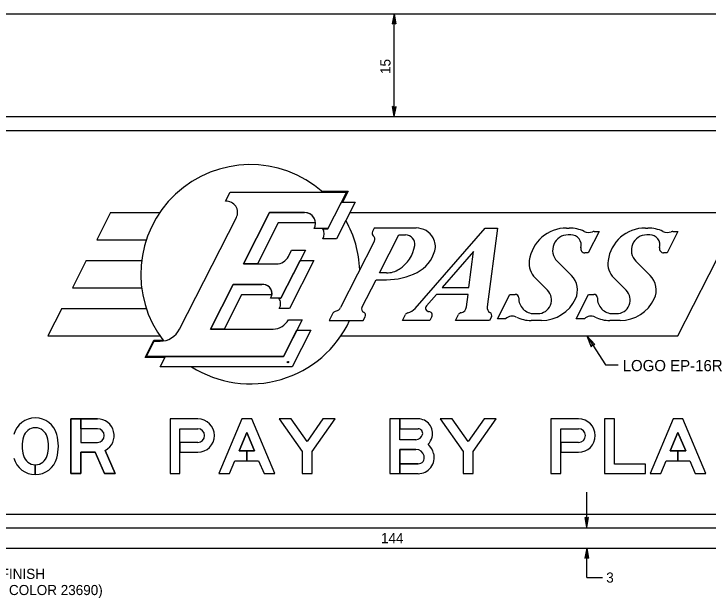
# Model space of a CAD drawing. Extents: x 60714 to 61340, y 9359 to 9729.
# Drawn here: x 60938.1 to 61130.7, y 9567 to 9729 of the extents above; entities that cross this region are included whole.
import ezdxf

# ---------------------------------------------------------------- set-up
doc = ezdxf.new("R2010")
doc.units = 0
for name, color, linetype in [('1', 7, 'Continuous'), ('2', 7, 'Continuous'), ('52', 7, 'Continuous'), ('GSBWFill', 7, 'Continuous'), ('SignPanel', 7, 'Continuous')]:
    doc.layers.add(name, color=color, linetype=linetype)

msp = doc.modelspace()

# ---------------------------------------------------------------- linework, layer by layer
at = {"layer": '1'}
for p, q in [((61043.58, 9700.47), (61043.58, 9728.97)), ((61097.05, 9639.67), (61102.28, 9631.67)), ((61102.28, 9631.67), (61105.72, 9631.67)), ((61097.05, 9586.47), (61097.05, 9596.36)), ((61097.05, 9572.66), (61097.05, 9580.77)), ((61097.05, 9572.66), (61101.45, 9572.66))]:
    msp.add_line(p, q, dxfattribs=at)
msp.add_circle((61014.12, 9632.42), 0.19, dxfattribs=at)
at = {"layer": '2'}
for p, q in [((60876.38, 9728.97), (61210.79, 9728.97)), ((60876.38, 9580.77), (61210.79, 9580.77))]:
    msp.add_line(p, q, dxfattribs=at)
at = {"layer": '52'}
for p, q in [((61043.58, 9728.97), (61043.05, 9726.21)), ((61043.58, 9728.97), (61043.31, 9726.32)), ((61043.58, 9728.97), (61044.03, 9726.19)), ((61043.58, 9728.97), (61043.77, 9726.31)), ((61043.05, 9726.21), (61043.54, 9726.41)), ((61043.54, 9726.41), (61044.03, 9726.19)), ((61043.58, 9700.47), (61043.14, 9703.25)), ((61043.63, 9703.03), (61043.14, 9703.25)), ((61043.58, 9700.47), (61043.4, 9703.13)), ((61043.58, 9700.47), (61044.12, 9703.23)), ((61043.58, 9700.47), (61043.86, 9703.12)), ((61044.12, 9703.23), (61043.63, 9703.03)), ((61097.05, 9639.67), (61098.29, 9636.63)), ((61099.31, 9637.3), (61097.05, 9639.67)), ((61098.29, 9636.63), (61098.68, 9637.18)), ((61098.68, 9637.18), (61099.31, 9637.3)), ((61097.03, 9586.55), (61096.59, 9589.32)), ((61097.08, 9589.1), (61096.59, 9589.32)), ((61097.03, 9586.55), (61096.85, 9589.21)), ((61097.03, 9586.55), (61097.57, 9589.31)), ((61097.03, 9586.55), (61097.31, 9589.2)), ((61097.57, 9589.31), (61097.08, 9589.1)), ((61097.05, 9580.77), (61096.51, 9578.01)), ((61097.05, 9580.77), (61096.77, 9578.12)), ((61097.05, 9580.77), (61097.49, 9577.99)), ((61097.05, 9580.77), (61097.23, 9578.11)), ((61096.51, 9578.01), (61097, 9578.21)), ((61097, 9578.21), (61097.49, 9577.99))]:
    msp.add_line(p, q, dxfattribs=at)
at = {"layer": 'GSBWFill'}
for p, q in [((60984.16, 9613.93), (60989.1, 9613.93)), ((60984.16, 9613.93), (60989.1, 9613.93)), ((60984.16, 9613.93), (60989.1, 9613.93)), ((61089.82, 9613.93), (61094.77, 9613.93)), ((61089.82, 9613.93), (61094.77, 9613.93)), ((61089.82, 9613.93), (61094.77, 9613.93)), ((60984.16, 9607.4), (60989.1, 9607.4)), ((61089.82, 9607.4), (61094.77, 9607.4)), ((60944.02, 9601.2), (60944.02, 9603.94)), ((60944.02, 9603.94), (60944.02, 9601.2)), ((60944.02, 9601.2), (60944.02, 9603.94)), ((60944.02, 9603.94), (60944.02, 9601.2)), ((61042.39, 9601.47), (61050.22, 9601.47))]:
    msp.add_line(p, q, dxfattribs=at)
for points in [[(60961.25, 9616.67), (60953.9, 9616.67), (60953.9, 9601.47), (60956.64, 9601.47), (60956.64, 9607.4), (60960.67, 9607.4), (60963.24, 9601.47), (60966.22, 9601.47), (60963.42, 9607.93)], [(60963.42, 9607.93), (60966.22, 9601.47), (60963.24, 9601.47), (60960.67, 9607.4), (60956.64, 9607.4), (60956.64, 9601.47), (60953.9, 9601.47), (60953.9, 9616.67), (60956.64, 9616.67), (60956.64, 9610.13), (60961.25, 9610.13)], [(60963.42, 9607.93), (60966.22, 9601.47), (60963.24, 9601.47), (60960.67, 9607.4), (60956.64, 9607.4), (60956.64, 9601.47), (60953.9, 9601.47), (60953.9, 9616.67), (60956.64, 9616.67), (60956.64, 9610.13), (60961.25, 9610.13)], [(60956.64, 9613.93), (60956.64, 9616.67), (60961.25, 9616.67)], [(60956.64, 9613.93), (60956.64, 9616.67), (60961.25, 9616.67)], [(60989.1, 9616.67), (60981.42, 9616.67), (60981.42, 9601.47), (60984.16, 9601.47), (60984.16, 9607.4)], [(60989.1, 9616.67), (60981.42, 9616.67), (60981.42, 9601.47), (60984.16, 9601.47), (60984.16, 9613.93)], [(60989.1, 9616.67), (60981.42, 9616.67), (60981.42, 9601.47), (60984.16, 9601.47), (60984.16, 9613.93)], [(61050.22, 9616.67), (61042.39, 9616.67), (61042.39, 9601.47)], [(61049.63, 9610.89), (61045.13, 9610.89), (61045.13, 9616.67), (61042.39, 9616.67), (61042.39, 9601.47), (61045.13, 9601.47)], [(61049.63, 9610.89), (61045.13, 9610.89), (61045.13, 9616.67), (61042.39, 9616.67), (61042.39, 9601.47), (61045.13, 9601.47)], [(61050.22, 9616.67), (61045.13, 9616.67), (61045.13, 9613.93), (61050.22, 9613.93)], [(61050.22, 9616.67), (61045.13, 9616.67), (61045.13, 9613.93), (61050.22, 9613.93)], [(61094.77, 9616.67), (61087.09, 9616.67), (61087.09, 9601.47), (61089.82, 9601.47), (61089.82, 9607.4)], [(61094.77, 9616.67), (61087.09, 9616.67), (61087.09, 9601.47), (61089.82, 9601.47), (61089.82, 9613.93)], [(61094.77, 9616.67), (61087.09, 9616.67), (61087.09, 9601.47), (61089.82, 9601.47), (61089.82, 9613.93)], [(60961.25, 9613.93), (60956.64, 9613.93), (60956.64, 9610.13), (60961.25, 9610.13)], [(60961.25, 9613.93), (60956.64, 9613.93)], [(60961.25, 9613.93), (60956.64, 9613.93)], [(60989.1, 9610.13), (60984.16, 9610.13), (60984.16, 9613.93)], [(61049.63, 9610.89), (61045.13, 9610.89), (61045.13, 9613.93), (61050.22, 9613.93)], [(61094.77, 9610.13), (61089.82, 9610.13), (61089.82, 9613.93)], [(60989.1, 9610.13), (60984.16, 9610.13), (60984.16, 9607.4), (60989.1, 9607.4)], [(60989.1, 9610.13), (60984.16, 9610.13), (60984.16, 9607.4), (60989.1, 9607.4)], [(61094.77, 9610.13), (61089.82, 9610.13), (61089.82, 9607.4), (61094.77, 9607.4)], [(61094.77, 9610.13), (61089.82, 9610.13), (61089.82, 9607.4), (61094.77, 9607.4)], [(61049.63, 9608.16), (61045.13, 9608.16), (61045.13, 9604.2), (61050.22, 9604.2)], [(61045.13, 9601.47), (61045.13, 9608.16), (61049.63, 9608.16)], [(61045.13, 9601.47), (61045.13, 9608.16), (61049.63, 9608.16)], [(61050.22, 9604.2), (61045.13, 9604.2), (61045.13, 9601.47), (61050.22, 9601.47)], [(61050.22, 9604.2), (61045.13, 9604.2), (61045.13, 9601.47), (61050.22, 9601.47)]]:
    msp.add_lwpolyline(points, dxfattribs=at)
for points in [[(60999.42, 9605.04), (61005.99, 9605.04), (61007.49, 9601.47), (61010.46, 9601.47), (61004.08, 9616.67), (61001.34, 9616.67), (60994.95, 9601.47), (60997.92, 9601.47)], [(61004.84, 9607.78), (61002.71, 9607.78), (61002.71, 9605.04), (61005.99, 9605.04), (61007.49, 9601.47), (61010.46, 9601.47), (61004.08, 9616.67), (61001.34, 9616.67), (60994.95, 9601.47), (60997.92, 9601.47), (60999.42, 9605.04), (61002.71, 9605.04), (61002.71, 9607.78), (61000.57, 9607.78), (61002.71, 9612.86)], [(61004.84, 9607.78), (61002.71, 9607.78), (61002.71, 9605.04), (61005.99, 9605.04), (61007.49, 9601.47), (61010.46, 9601.47), (61004.08, 9616.67), (61001.34, 9616.67), (60994.95, 9601.47), (60997.92, 9601.47), (60999.42, 9605.04), (61002.71, 9605.04), (61002.71, 9607.78), (61000.57, 9607.78), (61002.71, 9612.86)], [(61020.8, 9607.62), (61027.19, 9616.67), (61023.84, 9616.67), (61019.43, 9610.43), (61015.03, 9616.67), (61011.68, 9616.67), (61018.06, 9607.62), (61018.06, 9601.47), (61020.8, 9601.47)], [(61020.8, 9607.62), (61027.19, 9616.67), (61023.84, 9616.67), (61019.43, 9610.43), (61015.03, 9616.67), (61011.68, 9616.67), (61018.06, 9607.62), (61018.06, 9601.47), (61020.8, 9601.47)], [(61020.8, 9607.62), (61027.19, 9616.67), (61023.84, 9616.67), (61019.43, 9610.43), (61015.03, 9616.67), (61011.68, 9616.67), (61018.06, 9607.62), (61018.06, 9601.47), (61020.8, 9601.47)], [(61065.5, 9607.62), (61071.88, 9616.67), (61068.53, 9616.67), (61064.13, 9610.43), (61059.73, 9616.67), (61056.38, 9616.67), (61062.76, 9607.62), (61062.76, 9601.47), (61065.5, 9601.47)], [(61065.5, 9607.62), (61071.88, 9616.67), (61068.53, 9616.67), (61064.13, 9610.43), (61059.73, 9616.67), (61056.38, 9616.67), (61062.76, 9607.62), (61062.76, 9601.47), (61065.5, 9601.47)], [(61065.5, 9607.62), (61071.88, 9616.67), (61068.53, 9616.67), (61064.13, 9610.43), (61059.73, 9616.67), (61056.38, 9616.67), (61062.76, 9607.62), (61062.76, 9601.47), (61065.5, 9601.47)], [(61113.39, 9601.47), (61113.39, 9604.13), (61104.72, 9604.13), (61104.72, 9616.67), (61101.99, 9616.67), (61101.99, 9601.47)], [(61113.39, 9601.47), (61113.39, 9604.13), (61104.72, 9604.13), (61104.72, 9616.67), (61101.99, 9616.67), (61101.99, 9601.47)], [(61113.39, 9601.47), (61113.39, 9604.13), (61104.72, 9604.13), (61104.72, 9616.67), (61101.99, 9616.67), (61101.99, 9601.47)], [(61119.07, 9605.04), (61125.64, 9605.04), (61127.15, 9601.47), (61130.11, 9601.47), (61123.73, 9616.67), (61120.99, 9616.67), (61114.61, 9601.47), (61117.57, 9601.47)], [(61124.5, 9607.78), (61122.36, 9607.78), (61122.36, 9605.04), (61125.64, 9605.04), (61127.15, 9601.47), (61130.11, 9601.47), (61123.73, 9616.67), (61120.99, 9616.67), (61114.61, 9601.47), (61117.57, 9601.47), (61119.07, 9605.04), (61122.36, 9605.04), (61122.36, 9607.78), (61120.22, 9607.78), (61122.36, 9612.86)], [(61124.5, 9607.78), (61122.36, 9607.78), (61122.36, 9605.04), (61125.64, 9605.04), (61127.15, 9601.47), (61130.11, 9601.47), (61123.73, 9616.67), (61120.99, 9616.67), (61114.61, 9601.47), (61117.57, 9601.47), (61119.07, 9605.04), (61122.36, 9605.04), (61122.36, 9607.78), (61120.22, 9607.78), (61122.36, 9612.86)], [(61004.84, 9607.78), (61002.71, 9612.86), (61000.57, 9607.78)], [(61124.5, 9607.78), (61122.36, 9612.86), (61120.22, 9607.78)]]:
    msp.add_lwpolyline(points, close=True, dxfattribs=at)
for centre, radius, start, end in [((60944.02, 9610.77), 6.16, 14.9618, 165.0382), ((60944.02, 9610.77), 6.16, 14.9618, 165.0382), ((60944.02, 9610.77), 6.16, 14.9618, 165.0382), ((60961.25, 9612.03), 4.64, 297.837, 90), ((60961.25, 9612.03), 4.64, 297.837, 90), ((60961.25, 9612.03), 4.64, 297.837, 90), ((61050.22, 9612.64), 4.03, 345.5225, 90), ((61050.22, 9612.64), 4.03, 345.5225, 90), ((61050.22, 9612.64), 4.03, 345.5225, 90), ((60944.02, 9610.77), 3.42, 14.9618, 165.0382), ((60944.02, 9610.77), 3.42, 14.9618, 165.0382), ((60944.02, 9610.77), 3.42, 14.9618, 165.0382), ((60961.25, 9612.03), 1.9, 270, 90), ((60961.25, 9612.03), 1.9, 270, 90), ((60961.25, 9612.03), 1.9, 270, 90), ((61050.22, 9612.64), 1.29, 345.5225, 90), ((61050.22, 9612.64), 1.29, 345.5225, 90), ((61050.22, 9612.64), 1.29, 345.5225, 90), ((60950.41, 9609.07), 10.03, 165.0382, 194.9618), ((60950.41, 9609.07), 10.03, 165.0382, 194.9618), ((60950.41, 9609.07), 10.03, 165.0382, 194.9618), ((60937.64, 9609.07), 10.03, 345.0382, 14.9618), ((60937.64, 9609.07), 10.03, 345.0382, 14.9618), ((60937.64, 9609.07), 10.03, 345.0382, 14.9618), ((60937.64, 9609.07), 12.77, 345.0382, 14.9618), ((60937.64, 9609.07), 12.77, 345.0382, 14.9618), ((60937.64, 9609.07), 12.77, 345.0382, 14.9618), ((61049.63, 9612.79), 1.9, 270, 345.5225), ((61049.63, 9612.79), 1.9, 270, 345.5225), ((61049.63, 9612.79), 1.9, 270, 345.5225), ((61049.63, 9612.79), 4.64, 316.7114, 345.5225), ((61049.63, 9612.79), 4.64, 316.7114, 345.5225), ((61049.63, 9612.79), 4.64, 316.7114, 345.5225), ((61049.63, 9605.8), 5.09, 14.4775, 48.4921), ((61049.63, 9605.8), 5.09, 14.4775, 48.4921), ((61049.63, 9605.8), 5.09, 14.4775, 48.4921), ((61049.63, 9605.8), 2.36, 14.4775, 90), ((61049.63, 9605.8), 2.36, 14.4775, 90), ((61049.63, 9605.8), 2.36, 14.4775, 90), ((60944.02, 9607.36), 6.16, 194.9618, 345.0382), ((60944.02, 9607.36), 6.16, 194.9618, 270), ((60944.02, 9607.36), 6.16, 194.9618, 270), ((60944.02, 9607.36), 3.42, 194.9618, 345.0382), ((60944.02, 9607.36), 3.42, 194.9618, 270), ((60944.02, 9607.36), 3.42, 194.9618, 270), ((60944.02, 9607.36), 3.42, 270.0127, 345.0382), ((60944.02, 9607.36), 3.42, 270.0127, 345.0382), ((60944.02, 9607.36), 6.16, 270.0071, 345.0382), ((60944.02, 9607.36), 6.16, 270.0071, 345.0382), ((61050.22, 9605.95), 4.49, 270, 14.4775), ((61050.22, 9605.95), 4.49, 270, 14.4775), ((61050.22, 9605.95), 4.49, 270, 14.4775), ((61050.22, 9605.95), 1.75, 270, 14.4775), ((61050.22, 9605.95), 1.75, 270, 14.4775), ((61050.22, 9605.95), 1.75, 270, 14.4775)]:
    msp.add_arc(centre, radius, start, end, dxfattribs=at)
for centre, major_axis in [((60989.1, 9612.03), (0, 4.64)), ((60989.1, 9612.03), (0, 4.64)), ((60989.1, 9612.03), (0, 4.64)), ((61094.77, 9612.03), (0, 4.64)), ((61094.77, 9612.03), (0, 4.64)), ((61094.77, 9612.03), (0, 4.64)), ((60989.1, 9612.03), (0, 1.9)), ((60989.1, 9612.03), (0, 1.9)), ((60989.1, 9612.03), (0, 1.9)), ((61094.77, 9612.03), (0, 1.9)), ((61094.77, 9612.03), (0, 1.9)), ((61094.77, 9612.03), (0, 1.9))]:
    msp.add_ellipse(centre, major_axis=major_axis, ratio=0.999994, start_param=3.141593, end_param=6.283185, dxfattribs=at)
at = {"layer": 'SignPanel'}
for p, q in [((60921.98, 9700.47), (61165.18, 9700.47)), ((60921.98, 9696.67), (61165.18, 9696.67)), ((60996.81, 9677.02), (60998.1, 9679.57)), ((60998.1, 9679.57), (61030.4, 9679.57)), ((61023.46, 9679.85), (61030.87, 9679.85)), ((61030.4, 9679.57), (61025.23, 9669.41)), ((61030.87, 9679.85), (61029.27, 9676.72)), ((61025.22, 9669.4), (61028.96, 9676.72)), ((61025.22, 9669.4), (61028.96, 9676.72)), ((61032.79, 9676.72), (61027.62, 9666.56)), ((61032.79, 9676.72), (61027.62, 9666.56)), ((61028.96, 9676.72), (61032.79, 9676.72)), ((61028.96, 9676.72), (61032.79, 9676.72)), ((60964.92, 9673.87), (60961.06, 9666.27)), ((60964.92, 9673.87), (60978.55, 9673.87)), ((61009.05, 9673.87), (61001.79, 9659.62)), ((61001.79, 9659.62), (61009.05, 9673.87)), ((61001.79, 9659.62), (61009.05, 9673.87)), ((61018.74, 9673.87), (61009.05, 9673.87)), ((61009.05, 9673.87), (61018.74, 9673.87)), ((61009.05, 9673.87), (61018.74, 9673.87)), ((61031.34, 9673.87), (61139.72, 9673.87)), ((61122.3, 9639.67), (61139.72, 9673.87)), ((60984.04, 9641.52), (60999.81, 9672.47)), ((61011.44, 9671.02), (61005.63, 9659.62)), ((61011.44, 9671.02), (61005.63, 9659.62)), ((61021.77, 9671.02), (61011.44, 9671.02)), ((61021.77, 9671.02), (61011.44, 9671.02)), ((61025.23, 9669.41), (61021.43, 9669.41)), ((61023.81, 9669.4), (61025.22, 9669.4)), ((61023.81, 9669.4), (61025.22, 9669.4)), ((61038.07, 9669.59), (61037.56, 9668.58)), ((61049.71, 9669.59), (61038.07, 9669.59)), ((61049.42, 9647.28), (61068.82, 9669.59)), ((61068.82, 9669.59), (61072.24, 9669.59)), ((61072.24, 9669.59), (61069.4, 9647.73)), ((61091.46, 9669.59), (61092.18, 9669.59)), ((61113.31, 9669.59), (61114.03, 9669.59)), ((61039.56, 9657.15), (61044.94, 9667.69)), ((61044.94, 9667.69), (61046.77, 9667.69)), ((61092.66, 9667.69), (61091.85, 9667.69)), ((61100.5, 9668.64), (61097.48, 9662.72)), ((61099.07, 9668.64), (61100.5, 9668.64)), ((61114.51, 9667.69), (61113.7, 9667.69)), ((61122.35, 9668.64), (61119.33, 9662.72)), ((61120.92, 9668.64), (61122.35, 9668.64)), ((60961.06, 9666.27), (60974.81, 9666.27)), ((61027.62, 9666.56), (61023.82, 9666.56)), ((61027.62, 9666.56), (61023.82, 9666.56)), ((61038.11, 9666), (61028.7, 9647.54)), ((61018.95, 9663.42), (61012.17, 9650.12)), ((61014.27, 9661.69), (61015.15, 9663.42)), ((61015.15, 9663.42), (61018.95, 9663.42)), ((61065.64, 9663.04), (61056.96, 9653.06)), ((61064.34, 9653.06), (61065.64, 9663.04)), ((61097.48, 9662.72), (61096.53, 9662.72)), ((61119.33, 9662.72), (61118.38, 9662.72)), ((60958.16, 9660.57), (60954.29, 9652.97)), ((60958.16, 9660.57), (60973.52, 9660.57)), ((61001.79, 9659.62), (61010.88, 9659.62)), ((61005.63, 9659.62), (61001.79, 9659.62)), ((61005.63, 9659.62), (61001.79, 9659.62)), ((61012.17, 9650.12), (61017.5, 9660.57)), ((61012.17, 9650.12), (61017.5, 9660.57)), ((61021.33, 9660.57), (61014.56, 9647.27)), ((61021.33, 9660.57), (61014.56, 9647.27)), ((61017.5, 9660.57), (61021.33, 9660.57)), ((61017.5, 9660.57), (61021.33, 9660.57)), ((61088.82, 9660.4), (61092.8, 9656.41)), ((61110.67, 9660.4), (61114.66, 9656.41)), ((61041.45, 9657.15), (61039.56, 9657.15)), ((61086.14, 9652.33), (61082.72, 9655.75)), ((61107.99, 9652.33), (61104.57, 9655.75)), ((60998.89, 9653.92), (60992.6, 9641.57)), ((60992.6, 9641.57), (60998.89, 9653.92)), ((60992.6, 9641.57), (60998.89, 9653.92)), ((61007.23, 9653.92), (60998.89, 9653.92)), ((60998.89, 9653.92), (61006.87, 9653.89)), ((60998.89, 9653.92), (61006.87, 9653.89)), ((61034.67, 9647.54), (61038.6, 9655.25)), ((61038.6, 9655.25), (61041.45, 9655.25)), ((60954.29, 9652.97), (60973.52, 9652.97)), ((61056.96, 9653.06), (61064.34, 9653.06)), ((61001.27, 9651.06), (60996.43, 9641.57)), ((61001.27, 9651.06), (60996.43, 9641.57)), ((61009.66, 9651.04), (61001.27, 9651.06)), ((61009.66, 9651.04), (61001.27, 9651.06)), ((61012.17, 9650.12), (61009.31, 9650.12)), ((61011.57, 9650.12), (61012.17, 9650.12)), ((61011.57, 9650.12), (61012.17, 9650.12)), ((61055.32, 9651.16), (61052.56, 9648)), ((61064.15, 9651.16), (61055.32, 9651.16)), ((61063.7, 9647.73), (61064.15, 9651.16)), ((61072.23, 9644.42), (61075.68, 9651.19)), ((61075.68, 9651.19), (61077.2, 9651.19)), ((61094.08, 9644.42), (61097.53, 9651.19)), ((61097.53, 9651.19), (61099.05, 9651.19)), ((60951.38, 9647.27), (60947.52, 9639.67)), ((60951.38, 9647.27), (60974.81, 9647.27)), ((61014.56, 9647.27), (61011.71, 9647.27)), ((61014.56, 9647.27), (61011.71, 9647.27)), ((61026.39, 9645.62), (61025.54, 9643.94)), ((61035.04, 9643.94), (61035.55, 9644.96)), ((61045.92, 9643.94), (61046.75, 9645.57)), ((61054.08, 9645.04), (61053.52, 9643.94)), ((61060.58, 9643.94), (61061.42, 9645.59)), ((61070.58, 9644.92), (61070.08, 9643.94)), ((61074.54, 9644.42), (61072.23, 9644.42)), ((61082.42, 9645.84), (61083.45, 9645.84)), ((61096.38, 9644.42), (61094.08, 9644.42)), ((61104.28, 9645.84), (61105.3, 9645.84)), ((61018.05, 9644.13), (61012.87, 9633.97)), ((61014.25, 9644.13), (61018.05, 9644.13)), ((61025.54, 9643.94), (61035.04, 9643.94)), ((61053.52, 9643.94), (61045.92, 9643.94)), ((61070.08, 9643.94), (61060.58, 9643.94)), ((61084.47, 9643.94), (61081.62, 9643.94)), ((61106.32, 9643.94), (61103.46, 9643.94)), ((60992.6, 9641.57), (61010.03, 9641.57)), ((60996.43, 9641.57), (60992.6, 9641.57)), ((60996.43, 9641.57), (60992.6, 9641.57)), ((61012.87, 9633.97), (61016.6, 9641.28)), ((61012.87, 9633.97), (61016.6, 9641.28)), ((61020.44, 9641.28), (61015.26, 9631.12)), ((61020.44, 9641.28), (61015.26, 9631.12)), ((61016.6, 9641.28), (61020.44, 9641.28)), ((61016.6, 9641.28), (61020.44, 9641.28)), ((60947.52, 9639.67), (60978.55, 9639.67)), ((60974.47, 9633.72), (60976.88, 9638.45)), ((60976.88, 9638.45), (60978.62, 9638.45)), ((61028.82, 9639.67), (61122.3, 9639.67)), ((60974.87, 9633.97), (60977.03, 9638.2)), ((60977.03, 9638.2), (60978.62, 9638.2)), ((60980, 9633.72), (60974.47, 9633.72)), ((61012.87, 9633.97), (60974.87, 9633.97)), ((60978.67, 9631.12), (60980.12, 9633.97)), ((60978.67, 9631.12), (60980.12, 9633.97)), ((60980.12, 9633.97), (61012.87, 9633.97)), ((60980.12, 9633.97), (61012.87, 9633.97)), ((61015.26, 9631.12), (60978.67, 9631.12)), ((61015.26, 9631.12), (60978.67, 9631.12)), ((60921.98, 9590.27), (61165.18, 9590.27)), ((60921.98, 9586.47), (61165.18, 9586.47))]:
    msp.add_line(p, q, dxfattribs=at)
for centre, radius, start, end in [((61003.68, 9656.77), 30.4, 48.5904, 217.4727), ((60997.02, 9673.89), 3.14, 332.9998, 93.8045), ((61018.74, 9670.83), 3.04, 332.2089, 90), ((61018.74, 9670.83), 3.04, 3.5833, 90), ((61018.74, 9670.83), 3.04, 3.5833, 90), ((61003.68, 9656.77), 30.4, 2.4236, 29.2771), ((61021.12, 9667.98), 3.04, 332.2089, 27.9127), ((61021.12, 9667.98), 3.04, 332.2089, 27.9127), ((61049.71, 9664.18), 5.42, 29.4315, 90), ((61091.46, 9659.14), 10.45, 90, 172.3089), ((61092.18, 9660.09), 9.5, 64.0896, 90), ((61113.31, 9659.14), 10.45, 90, 172.3089), ((61114.03, 9660.09), 9.5, 64.0896, 90), ((61038.4, 9668.15), 0.95, 152.9784, 231.1602), ((61037.09, 9666.52), 1.14, 333.0027, 51.1602), ((61046.77, 9665.13), 2.57, 351.076, 90), ((61091.85, 9663.42), 4.28, 90, 225), ((61092.66, 9664.84), 2.85, 345.6915, 90), ((61097.57, 9671.2), 2.85, 244.0896, 292.0347), ((61099.07, 9667.5), 1.14, 90, 112.0347), ((61113.7, 9663.42), 4.28, 90, 225), ((61114.51, 9664.84), 2.85, 345.6915, 90), ((61119.42, 9671.2), 2.85, 244.0896, 292.0347), ((61120.92, 9667.5), 1.14, 90, 112.0347), ((61050.29, 9664.5), 4.75, 344.7074, 29.4315), ((61039.92, 9666.2), 9.5, 302.4206, 351.076), ((61096.53, 9663.86), 1.14, 165.6915, 270), ((61118.38, 9663.86), 1.14, 165.6915, 270), ((61010.88, 9663.42), 3.8, 270, 332.9883), ((61045.71, 9665.76), 9.5, 296.6431, 344.7074), ((61086.75, 9659.78), 5.7, 172.3089, 225), ((61108.6, 9659.78), 5.7, 172.3089, 225), ((61041.45, 9663.8), 6.65, 270, 302.4206), ((61041.45, 9674.25), 19, 270, 296.6431), ((61088.77, 9652.38), 5.7, 334.95, 45), ((61110.62, 9652.38), 5.7, 334.95, 45), ((61007.23, 9651.45), 2.47, 350.3502, 98.3344), ((61007.23, 9651.45), 2.47, 350.3502, 98.3344), ((61007.23, 9651.45), 2.47, 327.421, 90), ((61083.45, 9649.64), 3.8, 270, 45), ((61105.3, 9649.64), 3.8, 270, 45), ((61009.63, 9648.6), 2.47, 327.421, 37.9799), ((61009.63, 9648.6), 2.47, 327.421, 37.9799), ((61077.2, 9650.24), 0.95, 358.6664, 90), ((61082.43, 9650.12), 4.28, 178.6665, 270), ((61084.47, 9654.39), 10.45, 270, 334.95), ((61099.05, 9650.24), 0.95, 358.6664, 90), ((61104.28, 9650.12), 4.28, 178.6665, 270), ((61106.32, 9654.39), 10.45, 270, 334.95), ((61028.08, 9644.75), 1.9, 106.4317, 152.9742), ((61027.01, 9648.4), 1.9, 286.4317, 332.9959), ((61035.51, 9647.11), 0.95, 152.9884, 244.7832), ((61034.7, 9645.39), 0.95, 333.0239, 64.7832), ((61046.55, 9649.77), 3.8, 282.7162, 318.9966), ((61053.28, 9647.37), 0.95, 138.9824, 268.6869), ((61053.24, 9645.47), 0.95, 332.9784, 88.6869), ((61062.27, 9645.16), 0.95, 99.2397, 153.0239), ((61061.81, 9647.97), 1.9, 279.2397, 352.5632), ((61070.9, 9647.53), 1.52, 172.5884, 241.8673), ((61069.74, 9645.35), 0.95, 332.9784, 61.8673), ((61047.6, 9645.14), 0.95, 102.7162, 153.0239), ((61076.35, 9642.48), 2.66, 64.3795, 133.1892), ((61081.61, 9653.44), 9.5, 244.3795, 270), ((61098.21, 9642.48), 2.66, 64.3795, 133.1892), ((61103.46, 9653.44), 9.5, 244.3795, 270), ((61003.68, 9656.77), 30.4, 237.5383, 335.047), ((61010.03, 9646.32), 4.75, 270, 332.5096), ((60978.62, 9644.28), 6.08, 270, 332.9991), ((60978.62, 9644.28), 5.83, 270, 277.5038)]:
    msp.add_arc(centre, radius, start, end, dxfattribs=at)

# ---------------------------------------------------------------- texts
at = {"layer": '1'}
msp.add_text('15', height=2.8, rotation=90, dxfattribs=at).set_placement((61042.58, 9712.3))
for s, height, p in [('LOGO EP-16R', 3.1111, (61107.01, 9629.88)), ('144', 2.8, (61039.95, 9582.19)), ('LIGHT BEIGE SATIN FINISH', 2.8, (60897.8, 9572.28)), ('3', 2.8, (61102.45, 9571.26)), ('(FEDERAL STD. 595A COLOR 23690)', 2.8, (60897.8, 9567.8))]:
    msp.add_text(s, height=height, dxfattribs=at).set_placement(p)

doc.saveas('drawing.dxf')
